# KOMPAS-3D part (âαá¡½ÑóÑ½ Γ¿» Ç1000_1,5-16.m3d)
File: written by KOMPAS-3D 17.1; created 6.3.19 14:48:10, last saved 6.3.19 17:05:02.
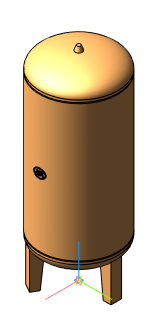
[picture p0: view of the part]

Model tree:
1. Операция без истории:1  (with: Сечение модели:1)

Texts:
  Гранлевел тип А100_1,5-16
  Гранлевел тип А150_1,5-16
  Гранлевел тип А220_1,5-16
  Гранлевел тип А350_1,5-16
  Гранлевел тип А500_1,5-16
  Гранлевел тип А700_1,5-16
  Гранлевел тип А900_1,5-16
  Гранлевел тип А1000_1,5-16
  Гранлевел тип А1400_1,5-16
  Точка начала. Х
  Точка начала. Y
  Точка начала. Z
